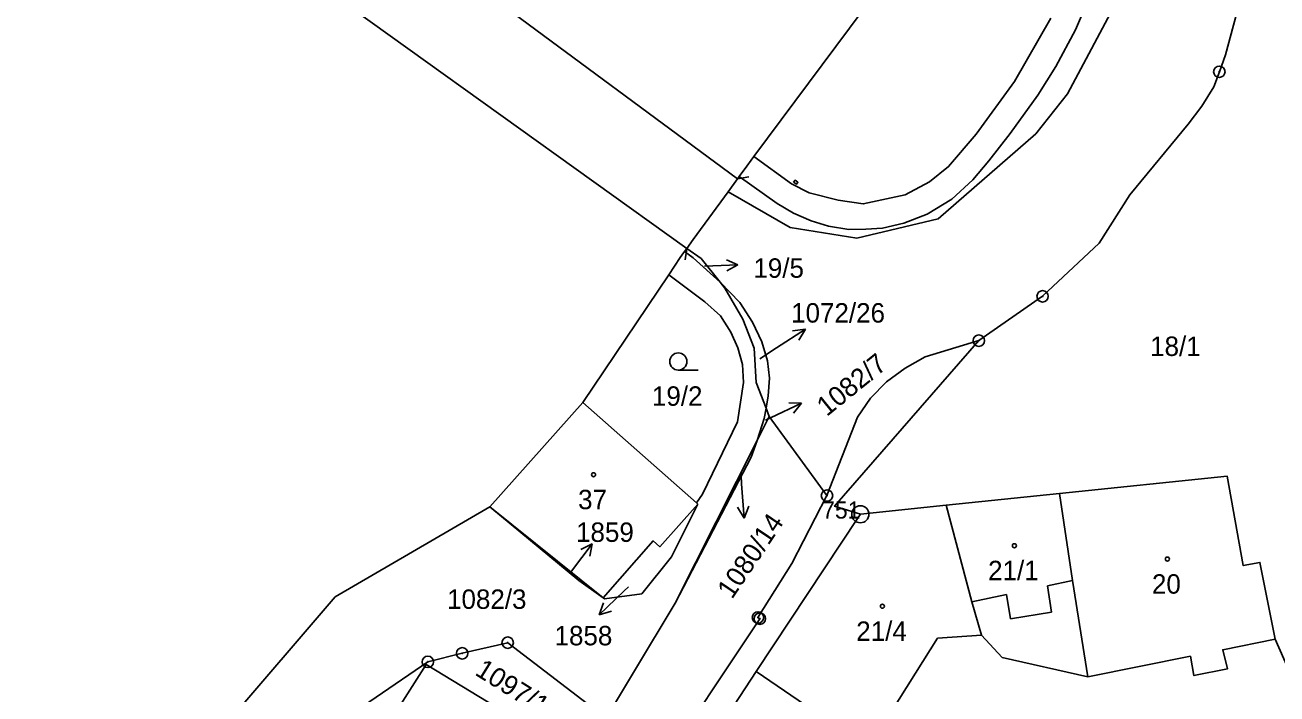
# Model space of a CAD drawing. Extents: x -680203 to -673936, y -1102717 to -1093650.
# Drawn here: x -678761 to -678651.4, y -1098666 to -1098607.5 of the extents above; entities that cross this region are included whole.
import ezdxf

# ---------------------------------------------------------------- set-up
doc = ezdxf.new("R2010")
doc.units = 0
for name, color, linetype in [('SOxx02xx_Koleje_param další_Popis10', 7, 'Continuous'), ('SOxx02xx_Staničení_Popis10', 7, 'Continuous'), ('SOxxxxxx_Koleje_hlavní_body_Popis10', 7, 'Continuous'), ('SOxxxxxx_Koleje_LN_parametry_Popis10', 7, 'Continuous'), ('SOxxxxxx_Koleje_param další_Popis10', 7, 'Continuous'), ('SOxxxxxx_Osa_bod_P', 7, 'Continuous'), ('SOxxxxxx_Staničení_Popis10', 7, 'Continuous'), ('x_prac', 7, 'Continuous')]:
    doc.layers.add(name, color=color, linetype=linetype)

msp = doc.modelspace()

# ---------------------------------------------------------------- linework, layer by layer
at = {"layer": 'SOxx02xx_Koleje_param další_Popis10'}
for centre, radius in [((-678656.43, -1098611.58), 0.5), ((-678656.43, -1098611.58), 0.0303), ((-678671.9, -1098631.23), 0.5), ((-678671.9, -1098631.23), 0.0303), ((-678677.48, -1098635.11), 0.5), ((-678677.48, -1098635.11), 0.0303), ((-678690.77, -1098648.67), 0.5), ((-678690.77, -1098648.67), 0.0303), ((-678687.85, -1098650.3), 0.75), ((-678687.85, -1098650.3), 0.03), ((-678696.81, -1098659.33), 0.5), ((-678696.65, -1098659.44), 0.5), ((-678696.81, -1098659.33), 0.0303), ((-678696.65, -1098659.44), 0.0303), ((-678718.71, -1098661.54), 0.5), ((-678722.69, -1098662.47), 0.5), ((-678718.71, -1098661.54), 0.0303), ((-678725.7, -1098663.22), 0.5), ((-678725.7, -1098663.22), 0.0303), ((-678722.69, -1098662.47), 0.0303)]:
    msp.add_circle(centre, radius, dxfattribs=at)
at = {"layer": 'SOxx02xx_Staničení_Popis10'}
for p, q in [((-678698.58, -1098628.49), (-678699.57, -1098628.04)), ((-678701.49, -1098628.59), (-678698.58, -1098628.49)), ((-678698.58, -1098628.49), (-678699.54, -1098629.01)), ((-678695.18, -1098635.75), (-678692.66, -1098634.12)), ((-678692.66, -1098634.12), (-678693.78, -1098634.24)), ((-678692.66, -1098634.12), (-678693.23, -1098635.08)), ((-678696.65, -1098636.7), (-678695.18, -1098635.75)), ((-678695.72, -1098641.85), (-678693, -1098640.58)), ((-678693, -1098640.58), (-678694.12, -1098640.55)), ((-678693, -1098640.58), (-678693.7, -1098641.46)), ((-678696.15, -1098642.06), (-678695.72, -1098641.85)), ((-678698.29, -1098646.88), (-678698.24, -1098647.64)), ((-678698.24, -1098647.64), (-678698.03, -1098650.63)), ((-678698.03, -1098650.63), (-678698.6, -1098649.67)), ((-678698.03, -1098650.63), (-678697.6, -1098649.6)), ((-678713.12, -1098655.28), (-678711.31, -1098652.88)), ((-678711.31, -1098652.88), (-678712.32, -1098653.38)), ((-678711.31, -1098652.88), (-678711.52, -1098653.98)), ((-678713.25, -1098655.45), (-678713.12, -1098655.28)), ((-678708.15, -1098656.64), (-678708.54, -1098657.03)), ((-678708.54, -1098657.03), (-678710.7, -1098659.11)), ((-678710.7, -1098659.11), (-678710.33, -1098658.06)), ((-678710.7, -1098659.11), (-678709.63, -1098658.78))]:
    msp.add_line(p, q, dxfattribs=at)
at = {"layer": 'SOxxxxxx_Koleje_hlavní_body_Popis10'}
msp.add_line((-678703.78, -1098637.69), (-678702.03, -1098637.69), dxfattribs=at)
msp.add_circle((-678703.78, -1098636.94), 0.75, dxfattribs=at)
at = {"layer": 'SOxxxxxx_Koleje_LN_parametry_Popis10'}
msp.add_lwpolyline([(-678693.69, -1098621.24), (-678693.44, -1098621.42), (-678693.31, -1098621.25), (-678693.56, -1098621.07)], close=True, dxfattribs=at)
at = {"layer": 'SOxxxxxx_Koleje_param další_Popis10'}
for centre in [(-678711.2, -1098646.84), (-678674.37, -1098653.05), (-678660.98, -1098654.22), (-678685.92, -1098658.35)]:
    msp.add_circle(centre, 0.175, dxfattribs=at)
at = {"layer": 'SOxxxxxx_Staničení_Popis10'}
for p, q in [((-678698.6, -1098620.95), (-678738.97, -1098591.09)), ((-678697.61, -1098620.78), (-678698.6, -1098620.95)), ((-678703.18, -1098628.03), (-678703.02, -1098627.04)), ((-678669.27, -1098656.1), (-678671.46, -1098656.57)), ((-678671.46, -1098656.57), (-678671.12, -1098658.88)), ((-678675.05, -1098657.33), (-678678.08, -1098657.97)), ((-678674.7, -1098659.45), (-678675.05, -1098657.33)), ((-678671.12, -1098658.88), (-678674.7, -1098659.45)), ((-678681.1, -1098661.15), (-678687.15, -1098670.77)), ((-678677.24, -1098660.87), (-678681.1, -1098661.15))]:
    msp.add_line(p, q, dxfattribs=at)
msp.add_lwpolyline([(-678746.16, -1098596.15), (-678743.73, -1098597.85), (-678703.02, -1098627.04)], dxfattribs=at)
at = {"layer": 'x_prac'}
for p, q in [((-678703.23, -1098627.32), (-678703.02, -1098627.04)), ((-678712.13, -1098640.51), (-678704.62, -1098629.34)), ((-678712.13, -1098640.51), (-678720.28, -1098649.64)), ((-678702.19, -1098649.29), (-678712.13, -1098640.51)), ((-678696.1, -1098641.03), (-678695.83, -1098641.74)), ((-678695.83, -1098641.74), (-678696.89, -1098643.84)), ((-678695.83, -1098641.74), (-678690.77, -1098648.67)), ((-678704.06, -1098658.08), (-678696.89, -1098643.84)), ((-678680.33, -1098649.52), (-678670.42, -1098648.49)), ((-678720.28, -1098649.64), (-678710.36, -1098657.61)), ((-678702.06, -1098649.41), (-678702.19, -1098649.29)), ((-678687.85, -1098650.3), (-678680.33, -1098649.52)), ((-678651.56, -1098661.24), (-678649.6, -1098665.66)), ((-678696.97, -1098664.05), (-678702.11, -1098671.9))]:
    msp.add_line(p, q, dxfattribs=at)
for points in [[(-678697.16, -1098619), (-678678.12, -1098593.43), (-678674.39, -1098588.42), (-678663.42, -1098562.67), (-678658.84, -1098548.37), (-678655.29, -1098530.31), (-678653.96, -1098521.25), (-678653.95, -1098517.06), (-678654.57, -1098513.13), (-678654.14, -1098507.91), (-678654, -1098506.17), (-678657.08, -1098505.44)], [(-678655.28, -1098551.32), (-678662.59, -1098593.58), (-678665.26, -1098605.12), (-678669.73, -1098613.51), (-678672.5, -1098617), (-678681.05, -1098624.46), (-678688.16, -1098626.13), (-678694, -1098625.21), (-678699.42, -1098622.08)], [(-678677.48, -1098635.11), (-678671.9, -1098631.23), (-678666.95, -1098626.58), (-678664.28, -1098622.35), (-678659.16, -1098616.18), (-678657.96, -1098614.59), (-678656.92, -1098612.9), (-678656.43, -1098611.58), (-678655.89, -1098610.11), (-678654.01, -1098603.04), (-678654.6, -1098594.6)], [(-678698.46, -1098620.76), (-678695.13, -1098623.11), (-678693.69, -1098623.96), (-678692.14, -1098624.62), (-678690.65, -1098625.08), (-678688.85, -1098625.39), (-678687.38, -1098625.37), (-678685.92, -1098625.27), (-678684.04, -1098624.83), (-678682.01, -1098624.04), (-678679.83, -1098622.73), (-678678, -1098621.04), (-678676.6, -1098619.39), (-678674.74, -1098616.99), (-678672.33, -1098613.63), (-678670.75, -1098611.13), (-678669.02, -1098607.9), (-678667.48, -1098604.28)], [(-678697.16, -1098619), (-678693.88, -1098621.38), (-678692.33, -1098622.18), (-678689.79, -1098622.83), (-678687.59, -1098623.14), (-678683.94, -1098622.35), (-678681.81, -1098621.21), (-678680.13, -1098619.88), (-678677.72, -1098617.04), (-678674.35, -1098612.43), (-678671.17, -1098606.89)], [(-678698.46, -1098620.76), (-678698.3, -1098620.55), (-678698.01, -1098620.15), (-678697.16, -1098619)], [(-678699.42, -1098622.08), (-678698.6, -1098620.95), (-678698.46, -1098620.76)], [(-678699.42, -1098622.08), (-678702.48, -1098626.27), (-678703.02, -1098627.04)], [(-678703.02, -1098627.04), (-678701.79, -1098627.93), (-678700.12, -1098629.99)], [(-678704.62, -1098629.34), (-678703.61, -1098627.84), (-678703.32, -1098627.44), (-678703.23, -1098627.32)], [(-678700.12, -1098629.99), (-678702.48, -1098627.86), (-678703.23, -1098627.32)], [(-678702.19, -1098649.29), (-678701.65, -1098648.55), (-678698.61, -1098642.2), (-678698.07, -1098638.76), (-678698.17, -1098637.21), (-678698.58, -1098635.74), (-678699.17, -1098634.38), (-678700.1, -1098632.95), (-678701.47, -1098631.7), (-678704.62, -1098629.34)], [(-678700.12, -1098629.99), (-678698.39, -1098631.77), (-678697.28, -1098633.48), (-678696.47, -1098635.2), (-678695.98, -1098636.88), (-678695.79, -1098638.39), (-678695.91, -1098639.93), (-678696.1, -1098641.03)], [(-678696.1, -1098641.03), (-678696.97, -1098638.78), (-678697.15, -1098635.77), (-678698.12, -1098633.22), (-678699.7, -1098630.52), (-678700.12, -1098629.99)], [(-678690.77, -1098648.67), (-678688.1, -1098641.82), (-678686.97, -1098640.14), (-678685.55, -1098638.71), (-678683.94, -1098637.51), (-678682.17, -1098636.52), (-678677.48, -1098635.11)], [(-678677.48, -1098635.11), (-678690.1, -1098649.6), (-678687.85, -1098650.3)], [(-678696.89, -1098643.84), (-678696.26, -1098641.93), (-678696.1, -1098641.03)], [(-678696.89, -1098643.84), (-678697.41, -1098645.3), (-678704.06, -1098658.08)], [(-678670.42, -1098648.49), (-678655.74, -1098646.97), (-678654.34, -1098654.79), (-678652.88, -1098654.51), (-678651.56, -1098661.24)], [(-678726.33, -1098703.16), (-678705.79, -1098673.17), (-678696.65, -1098659.44), (-678696.81, -1098659.33), (-678693.85, -1098654.61), (-678690.77, -1098648.67)], [(-678670.42, -1098648.49), (-678669.27, -1098656.1), (-678667.94, -1098664.54)], [(-678743.3, -1098668.57), (-678733.8, -1098657.53), (-678720.28, -1098649.64)], [(-678710.36, -1098657.61), (-678712.49, -1098656.11), (-678720.28, -1098649.64)], [(-678710.36, -1098657.61), (-678705.99, -1098652.63), (-678705.4, -1098653.15), (-678702.06, -1098649.41)], [(-678702.06, -1098649.41), (-678704.38, -1098654.02), (-678706.98, -1098657.25), (-678710.23, -1098657.7), (-678710.36, -1098657.61)], [(-678680.33, -1098649.52), (-678678.08, -1098657.97), (-678677.24, -1098660.87), (-678675.44, -1098662.83), (-678667.94, -1098664.54)], [(-678687.85, -1098650.3), (-678688.04, -1098650.58), (-678696.97, -1098664.05)], [(-678704.06, -1098658.08), (-678711.08, -1098669.78), (-678715.12, -1098675.97), (-678717.83, -1098680.11), (-678743.33, -1098719.17), (-678746.88, -1098726.6), (-678750.22, -1098736.88), (-678755.84, -1098767.58), (-678760.95, -1098779.31)], [(-678734.75, -1098669.4), (-678725.7, -1098663.22), (-678722.69, -1098662.47), (-678718.71, -1098661.54), (-678711.74, -1098666.89), (-678712.95, -1098668.68), (-678718.02, -1098676.25), (-678718.39, -1098676.95)], [(-678667.94, -1098664.54), (-678658.96, -1098662.73), (-678658.66, -1098664.42), (-678655.73, -1098663.83), (-678656.14, -1098662.16), (-678651.56, -1098661.24)], [(-678734.75, -1098669.4), (-678732.72, -1098670.67), (-678731.43, -1098668.56), (-678729.73, -1098669.54), (-678725.86, -1098663.44), (-678718.11, -1098668.14), (-678722.18, -1098674.53), (-678718.39, -1098676.95)], [(-678696.97, -1098664.05), (-678687.15, -1098670.77), (-678685.67, -1098672.41), (-678680.01, -1098678.7), (-678671.85, -1098688.09)]]:
    msp.add_lwpolyline(points, dxfattribs=at)

# ---------------------------------------------------------------- texts
at = {"layer": 'SOxx02xx_Koleje_param další_Popis10'}
msp.add_text('751', height=1.5, dxfattribs=at).set_placement((-678691.19, -1098650.68))
at = {"layer": 'SOxxxxxx_Osa_bod_P'}
for s, p in [('19/5', (-678697.21, -1098629.61)), ('1072/26', (-678693.91, -1098633.53)), ('18/1', (-678662.49, -1098636.45)), ('19/2', (-678706.09, -1098640.81)), ('37', (-678712.55, -1098649.86)), ('1859', (-678712.73, -1098652.72)), ('21/1', (-678676.67, -1098656.07)), ('20', (-678662.33, -1098657.25)), ('1082/3', (-678724.02, -1098658.58)), ('1858', (-678714.61, -1098661.77)), ('21/4', (-678688.21, -1098661.38))]:
    msp.add_text(s, height=1.7, dxfattribs=at).set_placement(p)
for s, rotation, p in [('1082/7', 39, (-678690.79, -1098641.8)), ('1080/14', 56, (-678699.08, -1098657.8)), ('1097/16', 328, (-678721.67, -1098664.3))]:
    msp.add_text(s, height=1.7, rotation=rotation, dxfattribs=at).set_placement(p)

doc.saveas('drawing.dxf')
